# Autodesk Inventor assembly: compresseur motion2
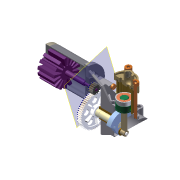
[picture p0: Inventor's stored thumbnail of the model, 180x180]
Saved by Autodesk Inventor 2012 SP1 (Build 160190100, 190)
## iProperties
Shininess: 41.0
Length Units: 11269
Angle Units: 11279
Time Units: 11290
Mass Units: 11283
Length Display Precision: 3
Angle Display Precision: 2
Created: 2002-11
Part Number: compresseur motion2
Document SubType Name: Assemblage
Designer: poste-2
Density: 0.0
Volumn: 0.0
Area: 0.0
PropertySet Name: Model Information
Control State: 0
Master: False
Checked Out: False
Author: poste-2
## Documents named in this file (6)
- C:\Users\Bruno\Desktop\cpù^resseur\TD_compresseur\compresseur motion.iam
- C:\Users\Bruno\Desktop\cpù^resseur\TD_compresseur\Ensemble corps.iam
- C:\Users\Bruno\Desktop\cpù^resseur\TD_compresseur\Ensemble moteur.iam
- C:\Users\Bruno\Desktop\cpù^resseur\TD_compresseur\Ensemble bielle.iam
- C:\Users\Bruno\Desktop\cpù^resseur\TD_compresseur\Ensemble piston.iam
- C:\Users\Bruno\Desktop\cpù^resseur\TD_compresseur\Ensemble manivelle.iam
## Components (5 placed, 5 different names)
1. Ensemble corps:1 [sub-assembly] — Logement:1, Plaquage:1, Plaquage:2, Plaquage:3
2. Ensemble moteur:1 [sub-assembly] — Logement:1
3. Ensemble bielle:1 [sub-assembly] — Plaquage:4, Plaquage:5, Plaquage:6
4. Ensemble piston:1 [sub-assembly] — Plaquage:1, Plaquage:5
5. Ensemble manivelle:1 [sub-assembly] — Plaquage:2, Plaquage:3, Plaquage:4, Plaquage:6
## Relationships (7: Mate 6, Insert 1)
- Logement:1 [Insert]: Ensemble corps:1 ↔ Ensemble moteur:1
- Plaquage:1 [Mate]: Ensemble corps:1 ↔ Ensemble piston:1
- Plaquage:2 [Mate]: Ensemble corps:1 ↔ Ensemble manivelle:1
- Plaquage:3 [Mate]: Ensemble corps:1 ↔ Ensemble manivelle:1
- Plaquage:4 [Mate]: Ensemble bielle:1 ↔ Ensemble manivelle:1
- Plaquage:5 [Mate]: Ensemble bielle:1 ↔ Ensemble piston:1
- Plaquage:6 [Mate]: Ensemble bielle:1 ↔ Ensemble manivelle:1
